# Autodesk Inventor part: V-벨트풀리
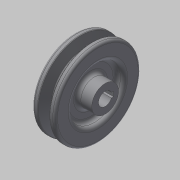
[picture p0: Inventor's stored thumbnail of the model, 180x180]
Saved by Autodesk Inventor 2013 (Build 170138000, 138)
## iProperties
Created: 2015-02
Part Number: V-벨트풀리
Material: 일반
Document SubType Name: Modeling
Designer: Administrator
Density: 1 g/cm^3
Author: Administrator
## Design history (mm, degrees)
sketch "스케치1"
  geometry: L1 (-12.5, 0)-(12.5, 0); L2 (-12.5, 0)-(-12.5, 11); L3 (-12.5, 11)-(-6.5, 11); L4 (-6.5, 11)-(-6.5, 21.5); L5 (-6.5, 21.5)-(-12.5, 21.5); L6 (-12.5, 21.5)-(-12.5, 35.2); L7 (-12.5, 35.2)-(-7.825, 35.2); L8 (-7.825, 35.2)-(-5.074, 26.2); L9 (-5.074, 26.2)-(-0.926, 26.2); L10 (-0.926, 26.2)-(1.825, 35.2); L11 (1.825, 35.2)-(6.5, 35.2); L12 (6.5, 35.2)-(6.5, 21.5); L13 (6.5, 21.5)-(0.5, 21.5); L14 (0.5, 21.5)-(0.5, 11); L15 (0.5, 11)-(12.5, 11); L16 (12.5, 11)-(12.5, 0); L17 (-16.359, 32.5)-(11.434, 32.5); 4 further points
  constraints: 34 end point, 9 parallel, 5 equal length, 4 point on line, 3 perpendicular, 2 collinear, 1 coincident, 1 horizontal, 1 midpoint
  dimensions: "d0" = 25 distance of L1.start L1.end; "d1" = 22 diameter of L3 L1; "d2" = 43 diameter of L5 L1; "d3" = 6 distance of L2.end L3.end; "d4" = 19 distance between parallel lines of L12 L6; "d5" = 0 distance between parallel lines of L6 L2; "d6" = 65 diameter of L17 L1; "d7" = 34 deg angle of L10 L8; "d8" = 8 distance of point (1, 32.5) point (-7, 32.5); "d9" = 22 diameter of L15 L1; "d17" = 6.3 distance between parallel lines of L17 L9; "d18" = 2.7 distance between parallel lines of L11 L17
revolve "회전1" sketch "스케치1" stored, may be unused: angle "d12" = 90 deg
sketch "스케치2"
  geometry: L1 (-2, 5.123)-(-2, 6.923); L2 (-2, 6.923)-(2, 6.923); L3 (2, 6.923)-(2, 5.123); C1 r 11 at (0, 0) reference; A1 r 5.5 centre (0, 0) between (-2, 5.123) and (2, 5.123)
  constraints: 6 end point, 2 point on circle, 1 centre point, 1 coincident, 1 parallel, 1 perpendicular, 1 vertical
  dimensions: "d13" = 11 diameter of A1; "d14" = 4 distance of L1.end L2.end; "d15" = 2 distance from line of C1.centre L3; "d16" = 1.8 distance of L2.end L3.end
extrude "돌출1" cut sketch "스케치2" distance "d19" = 31.75; taper "d20" = 0 deg
fillet "모깎기1" dims "d21" = 1
fillet "모깎기2" dims "d22" = 2
fillet "모깎기3" dims "d23" = 0.5
fillet "모깎기4" dims "d24" = 3
node "솔리드1"
